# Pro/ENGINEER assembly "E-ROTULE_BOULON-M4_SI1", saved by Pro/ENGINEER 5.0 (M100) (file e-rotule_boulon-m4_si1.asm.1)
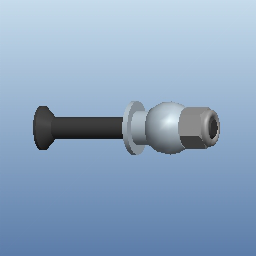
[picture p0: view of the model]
Units: millimeter Newton Second (mmNs); MM, TONNE, HOURS

Other components: 02-ROTULE_STD_SI1, VIS_FHC_M4X35, ECROU_H_FR_M4, RONDELLE_PLATE-D4

Other named items: 02-ROTULE_STD_V11, A-DROITE, A-DESSUS, A-FACE, A-R0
